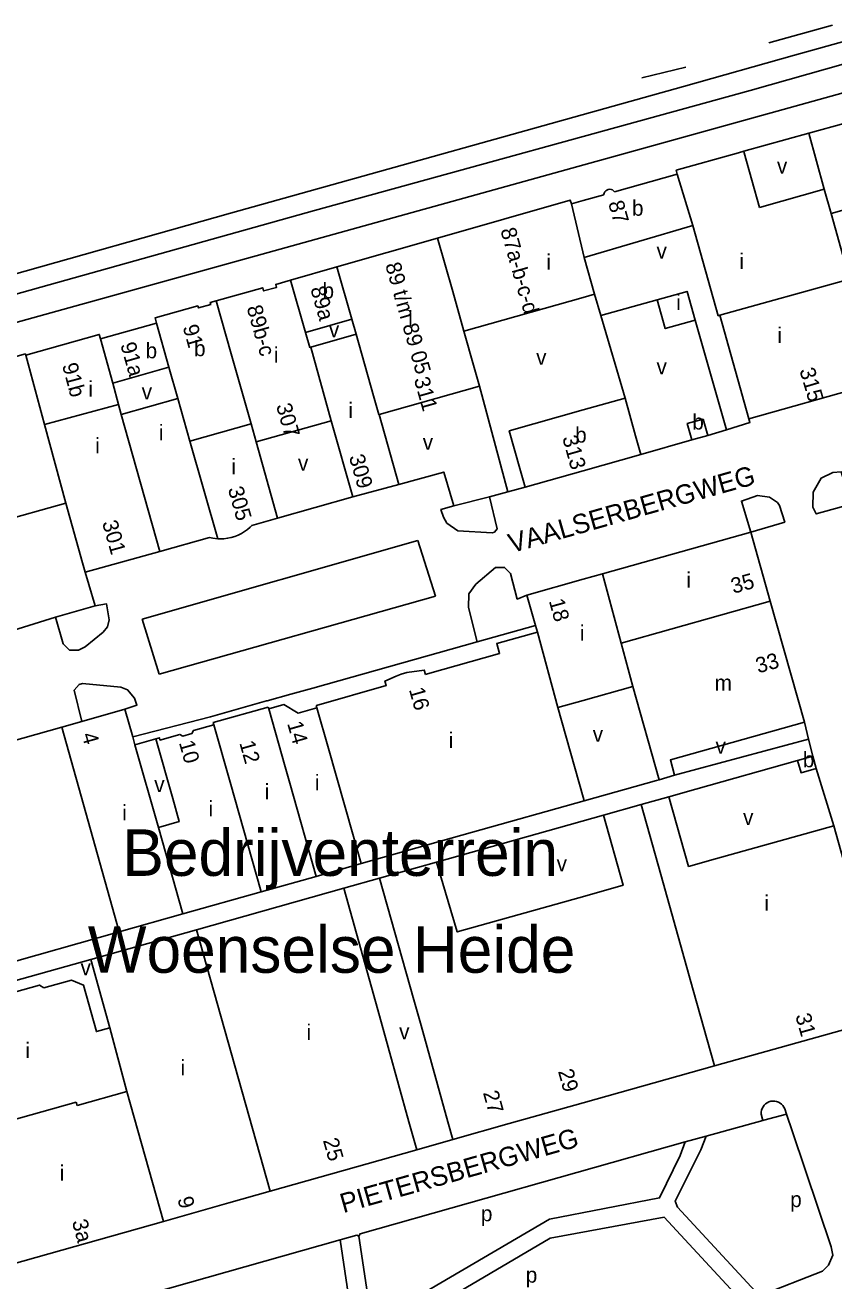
# Model space of a CAD drawing. Extents: x 159675 to 162108, y 386471 to 388472.
# Drawn here: x 159856.1 to 160064.7, y 387958.9 to 388282.9 of the extents above; entities that cross this region are included whole.
import ezdxf

# ---------------------------------------------------------------- set-up
doc = ezdxf.new("R2010")
doc.units = 0
for name, color, linetype in [('BLT_Basislijn', 7, 'Continuous'), ('BLT_Bebouwing', 7, 'Continuous'), ('BLT_Centroide', 7, 'Continuous'), ('BLT_Huisnummer', 7, 'Continuous'), ('BLT_Huisnummer_reeks', 7, 'Continuous'), ('BLT_Onderverdeling_panden', 7, 'Continuous'), ('BLT_Sport_parknaam', 7, 'Continuous'), ('BLT_Straatnaam', 7, 'Continuous')]:
    doc.layers.add(name, color=color, linetype=linetype)

msp = doc.modelspace()

# ---------------------------------------------------------------- linework, layer by layer
at = {"layer": 'BLT_Basislijn'}
for p, q in [((160015.15, 388269.34), (160026.53, 388272.11)), ((159823.15, 388197.77), (160070.19, 388266.36)), ((159930.76, 388235.12), (160043.08, 388266.1)), ((160041.45, 388250.39), (160058.23, 388255.06)), ((160058.23, 388255.06), (160067.61, 388257.67)), ((160058.23, 388255.06), (160062.21, 388240.64)), ((159823.15, 388204.98), (159930.76, 388235.12)), ((159823.15, 388210.19), (159909.05, 388234.42)), ((160004.57, 388208.03), (160002.96, 388213.52)), ((160019.15, 388212.04), (160004.57, 388208.03)), ((160010.82, 388186.7), (160004.57, 388208.03)), ((160028.88, 388206.8), (160036.96, 388178.54)), ((159973.29, 388189.81), (159980.63, 388162.55)), ((160036.96, 388178.54), (160032.15, 388177.04)), ((160014.93, 388172.13), (160028.06, 388175.91)), ((159921.22, 388155.73), (159940.61, 388161.23)), ((159966.68, 388158.91), (159975.86, 388161.24)), ((159980.63, 388162.55), (159975.86, 388161.24)), ((159980.63, 388162.55), (159985.07, 388163.73)), ((159957.37, 388150), (159961.96, 388135.56)), ((159872.52, 388138.59), (159871.59, 388141.77)), ((159874.11, 388133.06), (159872.52, 388138.59)), ((159874.11, 388133.06), (159863.95, 388130.16)), ((159863.95, 388130.16), (159845.51, 388124.49)), ((159886.31, 388129.67), (159890.65, 388115.48)), ((159972.72, 388123.84), (159987.73, 388128.04)), ((159930.27, 388111.86), (159972.72, 388123.84)), ((159924.58, 388110.31), (159930.27, 388111.86)), ((160058.18, 388098.71), (160057.08, 388103.07)), ((159889.8, 388098.8), (159884.4, 388097.27)), ((160058.18, 388098.71), (160023.62, 388089.42)), ((160059.28, 388094.33), (160058.18, 388098.71)), ((160029.07, 388085.82), (160055.35, 388093.22)), ((160064.65, 388076.34), (160060.17, 388091.16)), ((160022.13, 388083.86), (160029.07, 388085.82)), ((159962.2, 388066.98), (160005.28, 388079.11)), ((159938.33, 388060.28), (159947.53, 388062.86)), ((159847.84, 388034.8), (159873.02, 388041.86)), ((160045.98, 388001.95), (160046.35, 388000.3)), ((160052.47, 388001.96), (160046.63, 388000.38)), ((160052.47, 388001.96), (160052.02, 388003.28)), ((160046.35, 388000.3), (160031.73, 387996.24)), ((160046.63, 388000.38), (160046.35, 388000.3)), ((159966.45, 387995.38), (159957.12, 387992.73)), ((160026.3, 387994.79), (160031.73, 387996.24)), ((159937.34, 387969.56), (159868.3, 387950)), ((159937.34, 387969.56), (159939.72, 387953.37))]:
    msp.add_line(p, q, dxfattribs=at)
for points in [[(160047.93, 388278.37), (160064.32, 388282.94)], [(160043.08, 388266.1), (160067.72, 388273.04), (160069.47, 388276.04), (160070.01, 388277.69), (160069.09, 388279.21)], [(160069.09, 388279.21), (160054.57, 388275.18)], [(159909.05, 388234.42), (160025.93, 388267.09), (160054.57, 388275.18)], [(160042.79, 388181.34), (160043.06, 388180.44), (160036.96, 388178.54)], [(159966.68, 388158.91), (159964.06, 388167.62), (159952.47, 388164.43)], [(160069.17, 388159.32), (160066.57, 388167.7), (160064.4, 388167.54), (160061.44, 388166.05), (160059.34, 388162.47), (160059.31, 388158.53), (160060.17, 388156.83), (160069.17, 388159.32)], [(159966.68, 388158.91), (159963.35, 388157.93), (159963.97, 388156.02), (159964.88, 388154.47), (159967.68, 388152.48), (159976.57, 388151.91), (159977.14, 388152.1), (159977.84, 388152.99), (159975.86, 388161.24)], [(160043.28, 388152.12), (160052.03, 388154.7), (160050.71, 388159.03), (160050.14, 388159.77), (160048.06, 388161.1), (160045.04, 388161.57), (160040.87, 388160.11), (160043.28, 388152.12)], [(159886.31, 388129.67), (159957.37, 388150)], [(159985.53, 388135.87), (159983.04, 388134.83), (159981.28, 388141.43), (159979.76, 388143.02), (159977.4, 388142.98), (159972.3, 388138.68), (159970.53, 388136.21), (159970.46, 388132.66), (159972.72, 388123.84)], [(159961.96, 388135.56), (159890.65, 388115.48)], [(159874.11, 388133.06), (159877.09, 388133.58), (159877.79, 388129.48), (159877.32, 388127.66), (159876.23, 388126.33), (159871.53, 388122.5), (159869.82, 388121.64), (159867.53, 388121.68), (159865.92, 388123.28), (159863.95, 388130.16)], [(159881.82, 388106.43), (159884.9, 388107.43), (159884.31, 388109.26), (159882.49, 388111.43), (159880.78, 388112.14), (159870.87, 388113.04), (159869.98, 388112.77), (159868.75, 388111.33), (159870.73, 388103.29)], [(159924.58, 388110.31), (159918.55, 388108.61), (159918.36, 388108.55)], [(159883.84, 388099.26), (159903.88, 388104.43), (159918.36, 388108.55)], [(160000.25, 388082.82), (160018.95, 388088.03), (160019.6, 388088.22)], [(160045.98, 388001.95), (160045.98, 388002.45), (160046.06, 388002.95), (160046.21, 388003.42), (160046.44, 388003.86), (160046.74, 388004.26), (160047.09, 388004.61), (160047.5, 388004.9), (160047.95, 388005.12), (160048.42, 388005.27), (160048.92, 388005.33), (160049.42, 388005.32), (160049.91, 388005.23), (160050.38, 388005.06), (160050.81, 388004.82), (160051.21, 388004.51), (160051.54, 388004.14), (160051.82, 388003.72), (160052.02, 388003.28)], [(160052.47, 388001.96), (160054, 387997.35), (160064.04, 387967.73), (160064.39, 387965.58), (160063.28, 387963.01), (160061.73, 387961.45), (160045.55, 387955.08)], [(160031.73, 387996.24), (160030.42, 387992.77), (160023.8, 387979.49), (160024.35, 387977.93), (160045.55, 387955.08)], [(160026.3, 387994.79), (160025.05, 387991.3), (160019.74, 387980.33), (159991.38, 387974.82), (159946.32, 387948.47), (159945.42, 387948.74), (159942.18, 387970.46)], [(159942.18, 387970.46), (159942.49, 387971.03), (160026.3, 387994.79)], [(160041.22, 387953.41), (160020.93, 387975.35), (159991.48, 387969.93), (159946.57, 387943.44), (159946.25, 387943.02), (159947.46, 387916.89)], [(159942.18, 387970.46), (159941.61, 387970.7), (159937.34, 387969.56)]]:
    msp.add_lwpolyline(points, dxfattribs=at)
at = {"layer": 'BLT_Bebouwing'}
for p, q in [((160024.3, 388244.52), (160008.13, 388239.95)), ((160062.21, 388240.64), (160045.54, 388235.92)), ((160063.99, 388234.33), (160062.21, 388240.64)), ((160000.28, 388222.99), (160028.28, 388231.25)), ((159962.49, 388227.99), (159936.52, 388220.55)), ((160002.96, 388213.52), (160000.28, 388222.99)), ((159889.97, 388206.05), (159875.51, 388202.03)), ((159928.36, 388203.67), (159940.39, 388207.1)), ((159940.39, 388207.1), (159941.49, 388203.17)), ((160035.31, 388208.07), (160042.79, 388181.34)), ((159878.7, 388190.55), (159893.14, 388194.64)), ((159895.46, 388186.6), (159893.14, 388194.64)), ((159878.7, 388190.55), (159880.17, 388185.08)), ((160042.79, 388181.34), (160076.22, 388190.8)), ((159880.87, 388182.47), (159895.46, 388186.6)), ((159880.17, 388185.08), (159880.87, 388182.47)), ((159935.06, 388180.86), (159915.7, 388175.39)), ((159940.61, 388161.23), (159935.06, 388180.86)), ((159947.4, 388182.49), (159952.47, 388164.43)), ((160028.06, 388175.91), (160032.15, 388177.04)), ((159921.22, 388155.73), (159915.7, 388175.39)), ((159952.47, 388164.43), (159940.61, 388161.23)), ((159866.56, 388159.61), (159837.92, 388151.52)), ((159870.9, 388144.23), (159866.56, 388159.61)), ((160043.28, 388152.12), (160005, 388141.35)), ((160048.3, 388134.27), (160043.28, 388152.12)), ((159890.81, 388147.09), (159903.6, 388150.72)), ((159985.53, 388135.87), (159987.73, 388128.04)), ((160057.08, 388103.07), (160048.3, 388134.27)), ((159987.73, 388128.04), (159988.21, 388126.31)), ((160012.83, 388112.28), (160019.6, 388088.22)), ((159881.82, 388106.43), (159870.73, 388103.29)), ((159883.84, 388099.26), (159881.82, 388106.43)), ((159918.91, 388106.51), (159918.77, 388106.99)), ((159931.26, 388107.41), (159931.16, 388107.38)), ((159931.16, 388107.38), (159931.33, 388106.81)), ((159870.73, 388103.29), (159865.52, 388101.82)), ((159865.52, 388101.82), (159812.42, 388086.81)), ((159884.4, 388097.27), (159883.84, 388099.26)), ((159890.45, 388075.89), (159884.4, 388097.27)), ((160059.28, 388094.33), (160055.35, 388093.22)), ((160060.17, 388091.16), (160059.28, 388094.33)), ((160019.6, 388088.22), (160023.62, 388089.42)), ((159971.48, 388074.7), (160000.25, 388082.82)), ((160005.28, 388079.11), (160014.97, 388081.82)), ((159942.74, 388066.58), (159971.48, 388074.7)), ((159931.13, 388063.3), (159942.74, 388066.58)), ((159947.53, 388062.86), (159962.2, 388066.98)), ((159938.33, 388060.28), (159900.25, 388049.53)), ((159916.98, 388059.3), (159931.13, 388063.3)), ((159947.07, 388028.83), (159938.33, 388060.28)), ((159956.34, 388031.43), (159947.53, 388062.86)), ((159896.75, 388053.59), (159916.98, 388059.3)), ((159880.35, 388048.96), (159896.75, 388053.59)), ((159831.25, 388035.11), (159880.35, 388048.96)), ((159873.02, 388041.86), (159877.89, 388024.25)), ((159958.21, 388024.79), (159956.34, 388031.43)), ((159955.1, 388000), (159947.07, 388028.83)), ((159965.15, 388000), (159958.21, 388024.79)), ((160078.52, 388026.91), (160033.9, 388014.39)), ((159957.12, 387992.73), (159955.1, 388000)), ((159966.45, 387995.38), (159965.15, 388000)), ((159980.96, 387999.52), (159966.45, 387995.38)), ((159919.3, 387982.05), (159957.12, 387992.73)), ((159908.59, 387979.03), (159919.3, 387982.05)), ((159891.76, 387974.27), (159908.59, 387979.03)), ((159847.7, 387961.83), (159891.76, 387974.27))]:
    msp.add_line(p, q, dxfattribs=at)
for points in [[(160067.61, 388257.67), (160069.78, 388250), (160073.46, 388237), (160063.99, 388234.33)], [(160041.45, 388250.39), (160040.07, 388250), (160024.03, 388245.47), (160024.3, 388244.52)], [(160041.45, 388250.39), (160041.56, 388250), (160045.54, 388235.92)], [(160005.35, 388239.16), (160000, 388237.65), (159997, 388236.8)], [(160006.47, 388240.52), (160006.15, 388240.39), (160005.86, 388240.19), (160005.63, 388239.93), (160005.46, 388239.62), (160005.36, 388239.28), (160005.35, 388239.16)], [(160008.13, 388239.95), (160007.89, 388240.21), (160007.6, 388240.4), (160007.28, 388240.53), (160006.93, 388240.58), (160006.58, 388240.55), (160006.47, 388240.52)], [(159997, 388236.8), (159996.71, 388237.8), (159962.49, 388227.99)], [(160028.28, 388231.25), (160034.86, 388207.95), (160035.31, 388208.07)], [(159936.52, 388220.55), (159924.56, 388217.11)], [(159924.56, 388217.11), (159920.73, 388216.05), (159920.94, 388215.27), (159917.61, 388214.34), (159917.38, 388215.16), (159905.4, 388211.83)], [(159969.28, 388203.99), (160000, 388212.68), (160002.96, 388213.52)], [(160028.88, 388206.8), (160026.82, 388214.21), (160019.15, 388212.04)], [(159905.4, 388211.83), (159903.83, 388211.39), (159903.98, 388210.88), (159900.76, 388209.98), (159900.62, 388210.48), (159889.59, 388207.41), (159889.97, 388206.05)], [(160019.15, 388212.04), (160021.2, 388204.63), (160028.88, 388206.8)], [(159875.51, 388202.03), (159875.2, 388203.15), (159856.23, 388197.81)], [(159929.78, 388199.86), (159929.5, 388199.78), (159928.36, 388203.67)], [(159941.49, 388203.17), (159929.78, 388199.86)], [(159973.29, 388189.81), (159971.93, 388194.63), (159969.28, 388203.99)], [(159856.23, 388197.81), (159856.15, 388198.1), (159827.08, 388189.89)], [(159947.4, 388182.49), (159973.29, 388189.81)], [(159985.07, 388163.73), (159983.71, 388168.54), (159980.97, 388178.28), (160000, 388183.65), (160010.82, 388186.7)], [(160010.82, 388186.7), (160013.57, 388176.96), (160014.93, 388172.13)], [(160032.15, 388177.04), (160030.98, 388181.26), (160026.89, 388180.13), (160028.06, 388175.91)], [(160014.93, 388172.13), (160000, 388167.93), (159985.07, 388163.73)], [(159914.46, 388153.74), (159914.56, 388153.83), (159921.22, 388155.73)], [(159905.75, 388150.39), (159906.42, 388150.36), (159907.37, 388150.4), (159908.31, 388150.52), (159909.24, 388150.72), (159910.14, 388150.99), (159911.02, 388151.34), (159911.87, 388151.77), (159912.68, 388152.26), (159913.45, 388152.82), (159914.16, 388153.44), (159914.46, 388153.74)], [(159903.6, 388150.72), (159904.53, 388150.52), (159905.75, 388150.39)], [(159890.81, 388147.09), (159871.59, 388141.77)], [(159871.59, 388141.77), (159870.9, 388144.23)], [(160005, 388141.35), (160000, 388139.94), (159985.53, 388135.87)], [(159988.21, 388126.31), (159977.73, 388123.35), (159978.45, 388120.8), (159959.91, 388115.55)], [(159959.35, 388115.4), (159959.03, 388116.53), (159954.55, 388115.89), (159953.11, 388115.48), (159951.78, 388114.94), (159948.9, 388113.68), (159949.23, 388112.53), (159931.26, 388107.41)], [(159959.91, 388115.55), (159959.35, 388115.4)], [(159993.49, 388106.84), (160000, 388108.67), (160012.83, 388112.28)], [(159918.77, 388106.99), (159904.61, 388102.99), (159904.78, 388102.41)], [(159918.91, 388106.51), (159922.8, 388107.61), (159926.51, 388105.45), (159931.33, 388106.81)], [(160000.25, 388082.82), (160000, 388083.7), (159993.49, 388106.84)], [(159904.78, 388102.41), (159899.49, 388100.92), (159899.09, 388100.13), (159896.73, 388099.46), (159896.02, 388099.93), (159890.87, 388098.48), (159890.71, 388099.05), (159889.8, 388098.8)], [(160023.62, 388089.42), (160022.52, 388093.34), (160057.08, 388103.07)], [(159889.8, 388098.8), (159894.16, 388083.38)], [(160055.35, 388093.22), (160056.24, 388090.05), (160060.17, 388091.16)], [(159894.16, 388083.38), (159895.85, 388077.42), (159890.45, 388075.89)], [(160014.97, 388081.82), (160022.13, 388083.86)], [(160022.13, 388083.86), (160027.2, 388065.87), (160034.13, 388067.81), (160064.65, 388076.34)], [(159962.2, 388066.98), (159967.56, 388048.96), (160001.08, 388058.4), (160010.38, 388061.02), (160005.28, 388079.11)], [(160064.65, 388076.34), (160077.42, 388030.82)], [(159900.25, 388049.53), (159873.02, 388041.86)], [(159847.84, 388034.8), (159848.85, 388031.17), (159852.7, 388032.26), (159853.3, 388033.39), (159859.77, 388035.23), (159860.89, 388034.58)], [(159860.89, 388034.58), (159868.06, 388036.55), (159871.15, 388035.22), (159874.49, 388023.23), (159877.89, 388024.25)], [(160033.9, 388014.39), (160000, 388004.88), (159980.96, 387999.52)]]:
    msp.add_lwpolyline(points, dxfattribs=at)
at = {"layer": 'BLT_Onderverdeling_panden'}
for p, q in [((160024.3, 388244.52), (160028.28, 388231.25)), ((160000.28, 388222.99), (159997, 388236.8)), ((160063.99, 388234.33), (160067.55, 388221.66)), ((159966.39, 388214.23), (159962.49, 388227.99)), ((159940.39, 388207.1), (159936.52, 388220.55)), ((159928.36, 388203.67), (159924.56, 388217.11)), ((160035.31, 388208.07), (160068.74, 388217.42)), ((159969.28, 388203.99), (159966.39, 388214.23)), ((159909.26, 388198.16), (159905.4, 388211.83)), ((159893.14, 388194.64), (159889.97, 388206.05)), ((159878.7, 388190.55), (159875.51, 388202.03)), ((159935.06, 388180.86), (159929.78, 388199.86)), ((159856.23, 388197.81), (159861.08, 388179.86)), ((159914.37, 388180.08), (159909.26, 388198.16)), ((159895.46, 388186.6), (159898.55, 388175.63)), ((159861.08, 388179.86), (159880.17, 388185.08)), ((159880.87, 388182.47), (159890.81, 388147.09)), ((159898.55, 388175.63), (159914.37, 388180.08)), ((159915.7, 388175.39), (159914.37, 388180.08)), ((159861.08, 388179.86), (159866.56, 388159.61)), ((159898.55, 388175.63), (159905.75, 388150.39)), ((160005, 388141.35), (160009.82, 388123.45)), ((160048.3, 388134.27), (160009.82, 388123.45)), ((159988.21, 388126.31), (159993.49, 388106.84)), ((160009.82, 388123.45), (160012.83, 388112.28)), ((159923.13, 388091.58), (159918.91, 388106.51)), ((159931.33, 388106.81), (159934.31, 388096.33)), ((159904.78, 388102.41), (159908.98, 388087.58)), ((159865.52, 388101.82), (159880.35, 388048.96)), ((159934.31, 388096.33), (159942.74, 388066.58)), ((159924.32, 388087.35), (159923.13, 388091.58)), ((159908.98, 388087.58), (159916.98, 388059.3)), ((159924.32, 388087.35), (159931.13, 388063.3)), ((160020.03, 388063.81), (160014.97, 388081.82)), ((159890.45, 388075.89), (159896.75, 388053.59)), ((160024.53, 388047.78), (160020.03, 388063.81)), ((159919.3, 387982.05), (159900.25, 388049.53)), ((160028.41, 388033.94), (160024.53, 388047.78)), ((160033.9, 388014.39), (160028.41, 388033.94)), ((159882.3, 388007.76), (159877.89, 388024.25)), ((159837.99, 387996.24), (159869.23, 388005.06)), ((159869.49, 388004.14), (159869.23, 388005.06)), ((159869.49, 388004.14), (159882.3, 388007.76)), ((159891.76, 387974.27), (159882.3, 388007.76))]:
    msp.add_line(p, q, dxfattribs=at)
msp.add_lwpolyline([(159941.49, 388203.17), (159945.92, 388187.27), (159947.29, 388182.46), (159947.4, 388182.49)], dxfattribs=at)

# ---------------------------------------------------------------- texts
at = {"layer": 'BLT_Centroide'}
for s, p in [('v', (160050.01, 388244.64)), ('b', (160012.62, 388233.75)), ('v', (160018.95, 388222.71)), ('i', (159990.54, 388219.84)), ('i', (160040.34, 388220.04)), ('b', (159932.8, 388212.44)), ('i', (160024.02, 388209.41)), ('i', (159954.91, 388205.22)), ('v', (159934.44, 388202.41)), ('i', (160050.12, 388200.95)), ('b', (159887.16, 388196.97)), ('b', (159899.65, 388197.52)), ('i', (159920.23, 388195.86)), ('v', (159987.89, 388195.3)), ('v', (160018.95, 388192.86)), ('i', (159872.39, 388187.09)), ('v', (159886.15, 388186.38)), ('i', (159939.45, 388181.58)), ('i', (159890.58, 388175.83)), ('b', (160028.18, 388178.59)), ('b', (159997.95, 388175.22)), ('i', (159874.16, 388172.44)), ('v', (159958.65, 388173.37)), ('i', (159909.27, 388167.05)), ('v', (159926.46, 388167.97)), ('i', (160026.64, 388137.78)), ('i', (159999.17, 388124.08)), ('m', (160033.95, 388111.25)), ('i', (159965.34, 388096.44)), ('v', (160002.5, 388098.02)), ('v', (160034.17, 388094.97)), ('b', (160056.69, 388091.45)), ('i', (159930.83, 388085.53)), ('v', (159889.38, 388085.05)), ('i', (159917.88, 388083.16)), ('i', (159903.39, 388078.75)), ('i', (159881.14, 388077.72)), ('v', (160041.27, 388076.57)), ('v', (159993.18, 388064.63)), ('i', (160046.75, 388054.41)), ('v', (159870.38, 388037.79)), ('i', (159990.72, 388038.59)), ('i', (159928.69, 388021.12)), ('v', (159952.56, 388021.27)), ('i', (159856.14, 388016.41)), ('i', (159896.16, 388011.94)), ('i', (159865, 387984.78)), ('p', (160053.43, 387977.96)), ('p', (159973.65, 387974.31)), ('p', (159985.22, 387958.47))]:
    msp.add_text(s, height=4, dxfattribs=at).set_placement(p)
at = {"layer": 'BLT_Huisnummer'}
for s, rotation, p in [('87', 285.776, (160006.44, 388237.08)), ('89a', 285.7745, (159929.62, 388214.98)), ('91', 285.7738, (159896.69, 388205.08)), ('91a', 285.7752, (159880.6, 388200.53)), ('313', 285.7502, (159994.59, 388176.49)), ('309', 286.1338, (159939.56, 388171.58)), ('305', 285.7769, (159908.34, 388163.32)), ('35', 15.7144, (160038.78, 388136.19)), ('18', 285.7189, (159991.14, 388134.39)), ('33', 15.7144, (160045.17, 388115.65)), ('16', 285.811, (159955.06, 388111.51)), ('14', 285.81, (159923.64, 388102.77)), ('4', 285.7854, (159870.63, 388099.86)), ('10', 285.8104, (159895.72, 388097.81)), ('12', 285.8112, (159911.3, 388097.75)), ('31', 285.6786, (160054.71, 388027.38)), ('25', 285.7688, (159932.87, 387995.21)), ('9', 285.769, (159895.31, 387980.1))]:
    msp.add_text(s, height=4, rotation=rotation, dxfattribs=at).set_placement(p)
at = {"layer": 'BLT_Huisnummer_reeks'}
for s, rotation, p in [('87a-b-c-d', 285.7886, (159978.64, 388230.09)), ('89 t/m 89 05', 285.7788, (159948.93, 388221.14)), ('89b-c', 285.7745, (159913.19, 388210.09)), ('91b', 285.0275, (159865.58, 388195.23)), ('315', 286.5936, (160055.77, 388193.93)), ('311', 285.7927, (159956.32, 388191.59)), ('307', 285.7741, (159920.78, 388184.79)), ('301', 285.7769, (159875.9, 388154.6)), ('29', 285.662, (159993.5, 388013.03)), ('27', 285.662, (159974.15, 388007.47)), ('3a', 285.1229, (159868.12, 387974.25))]:
    msp.add_text(s, height=4, rotation=rotation, dxfattribs=at).set_placement(p)
at = {"layer": 'BLT_Sport_parknaam'}
for s, p in [('Bedrijventerrein', (159881.17, 388063.43)), ('Woenselse Heide', (159872.25, 388038.43))]:
    msp.add_text(s, height=12, dxfattribs=at).set_placement(p)
at = {"layer": 'BLT_Straatnaam'}
for s, height, rotation, p in [('VAALSERBERGWEG', 5, 15.8246, (159981.56, 388146.67)), ('PIETERSBERGWEG', 4.9999, 15.8012, (159938.14, 387976.39))]:
    msp.add_text(s, height=height, rotation=rotation, dxfattribs=at).set_placement(p)

doc.saveas('drawing.dxf')
